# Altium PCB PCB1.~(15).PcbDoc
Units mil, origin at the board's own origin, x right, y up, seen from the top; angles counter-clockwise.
Board outline 3715 x 2925 mil, 2 copper layers (Top Layer, Bottom Layer); 4 components, 37 nets, 176 pads, 0 vias.
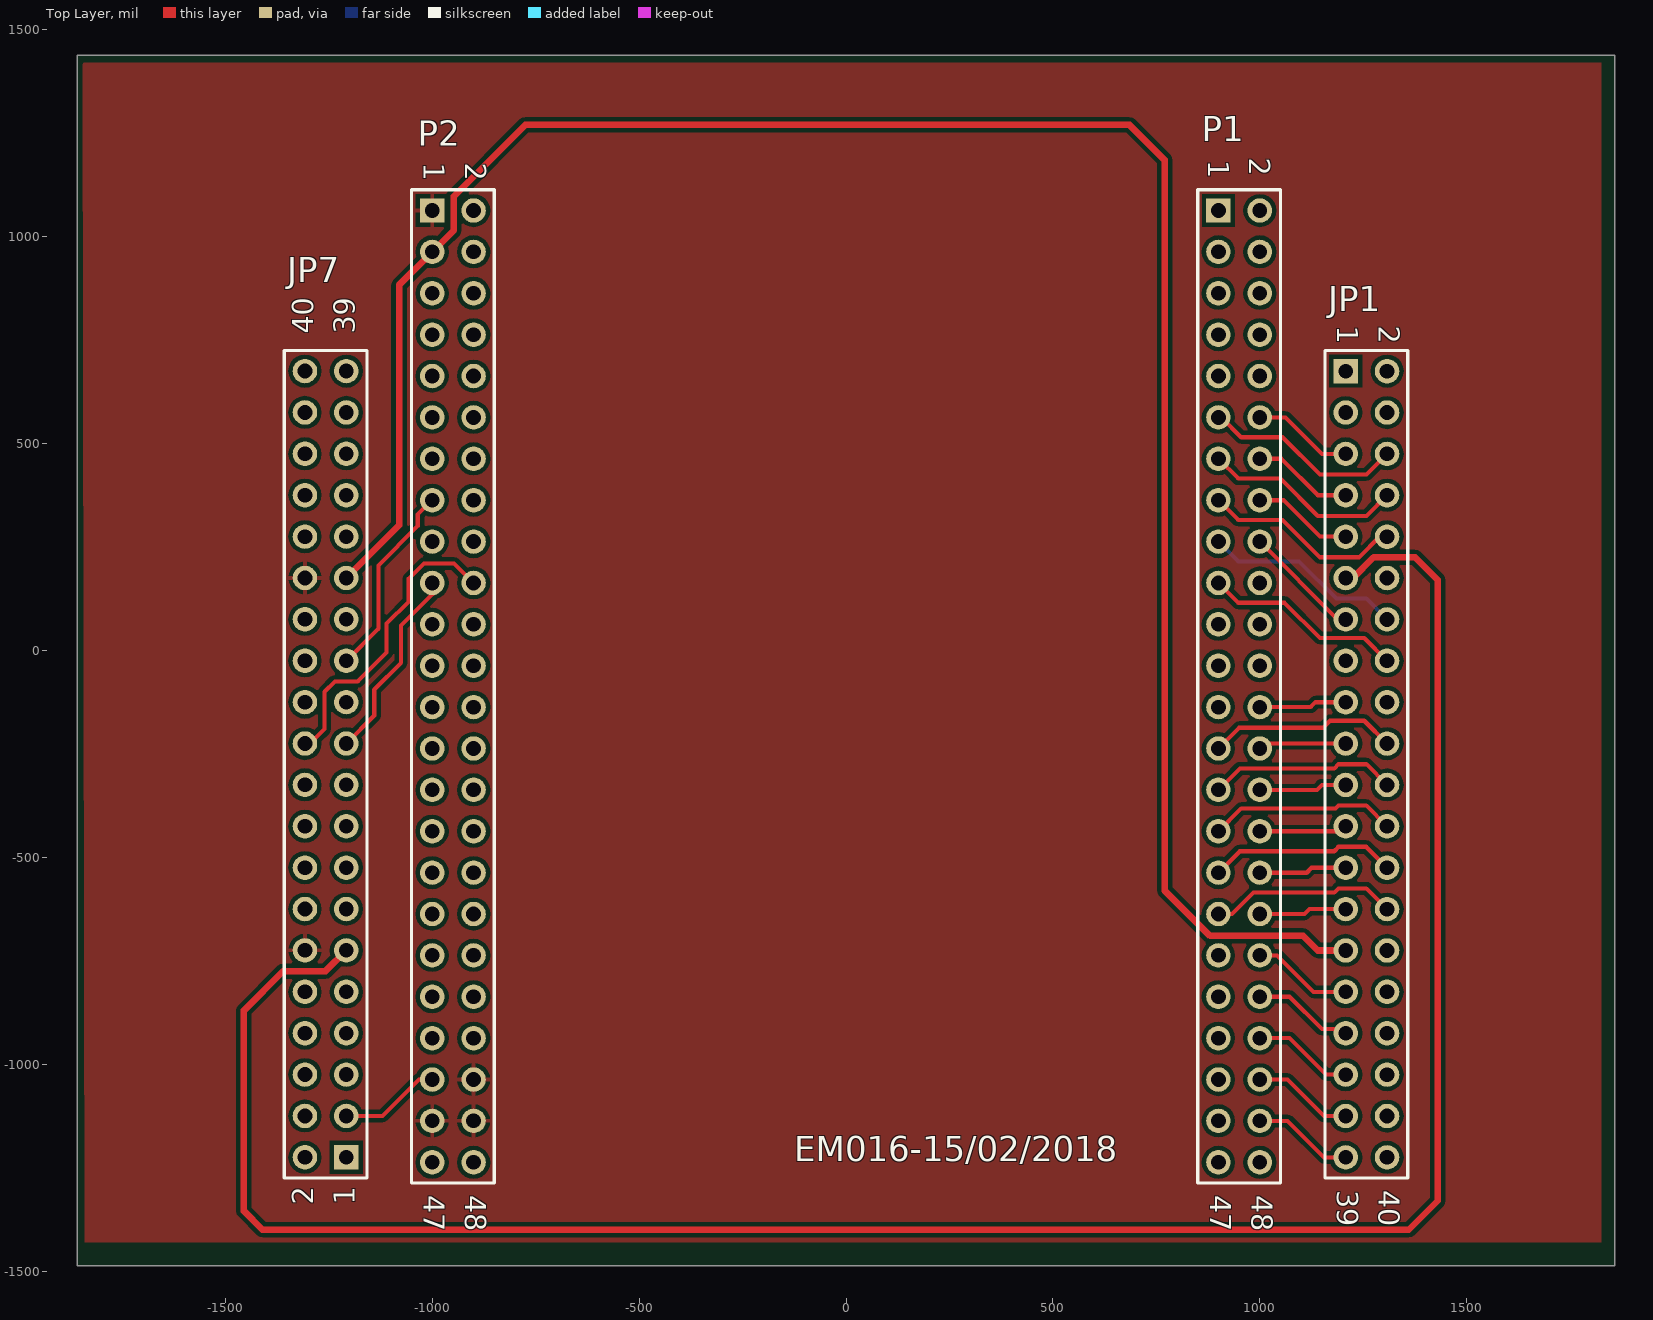
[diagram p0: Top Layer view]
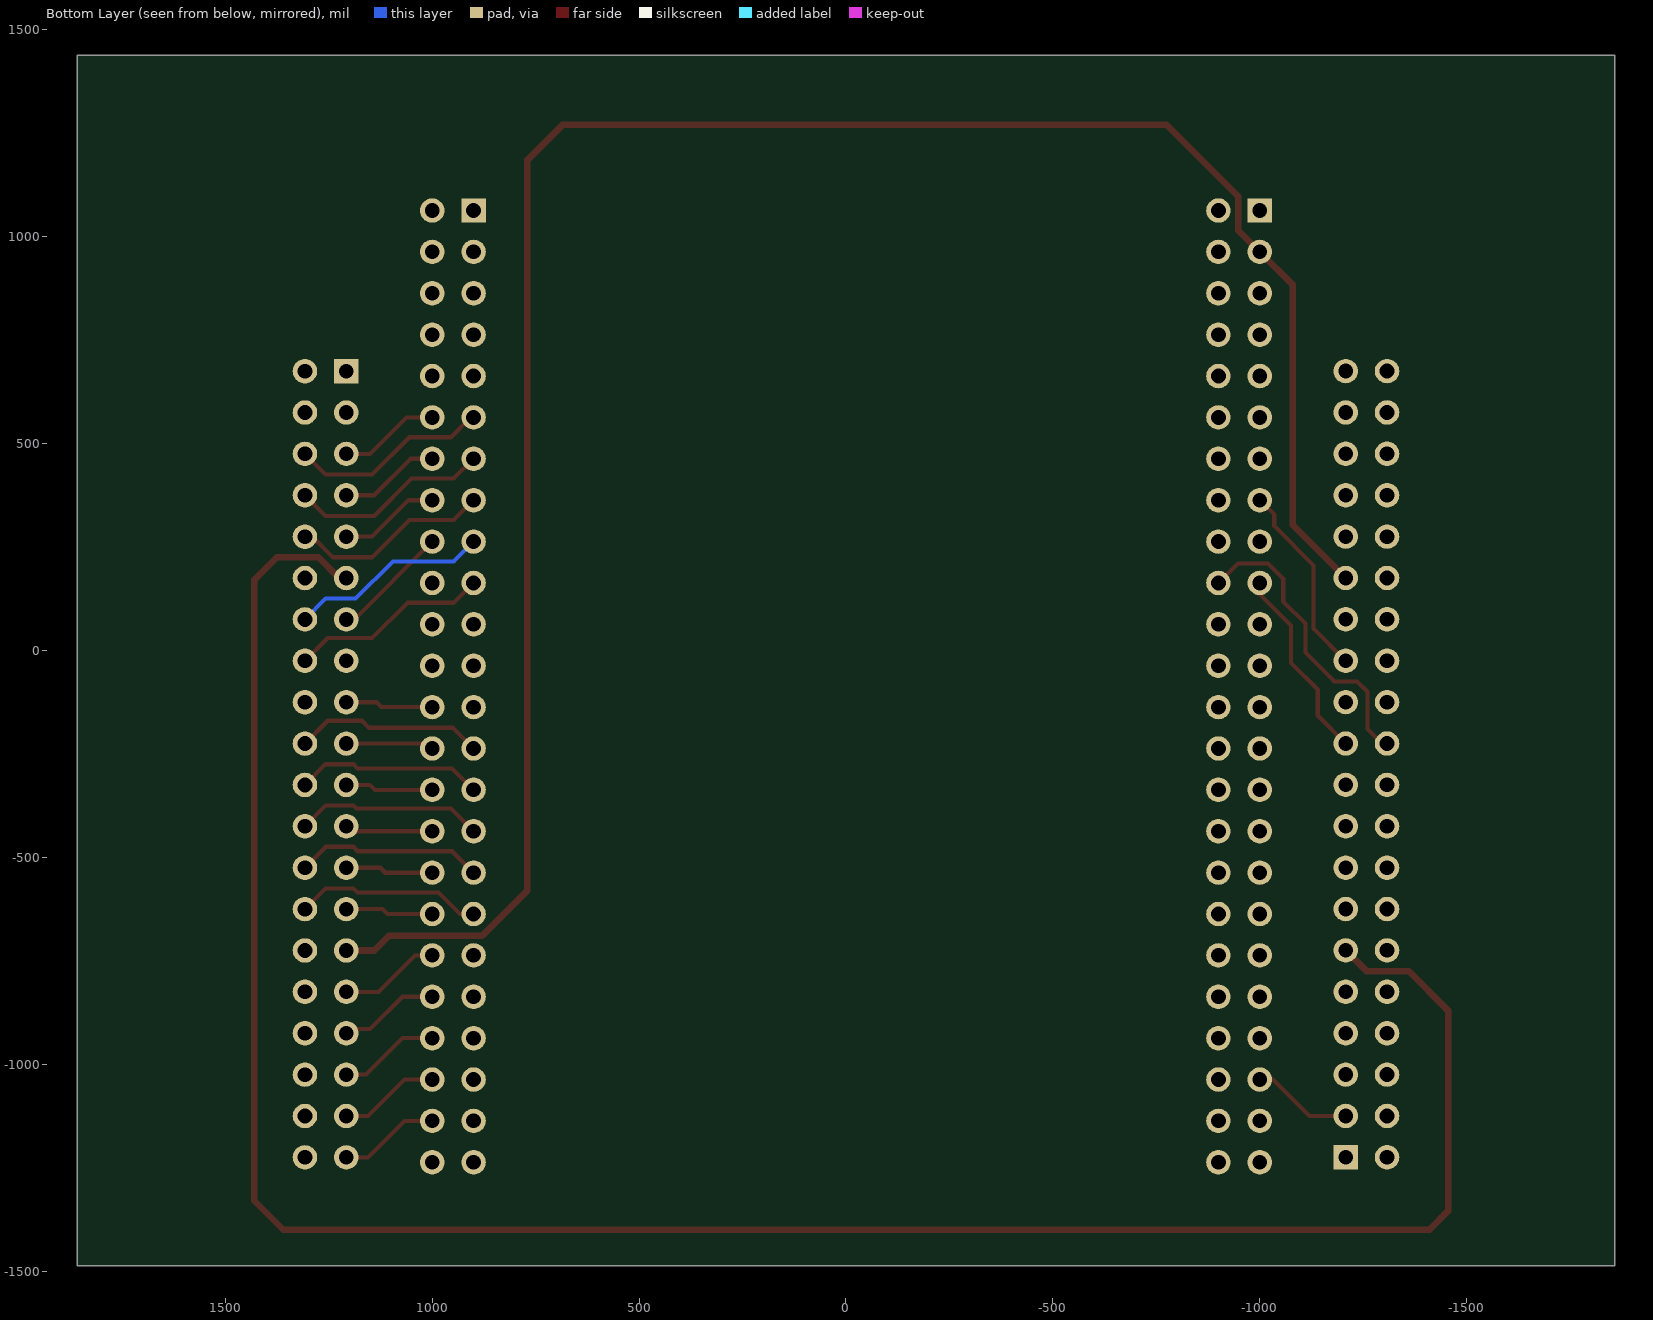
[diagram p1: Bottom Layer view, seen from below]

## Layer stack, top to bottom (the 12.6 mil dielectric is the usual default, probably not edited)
Top Solder: solder mask 0.4, Solder Resist, Dk 3.5
Top Layer: signal copper 1.4
Dielectric 1: dielectric 12.6, FR-4, Dk 4.8
Bottom Layer: signal copper 1.4
Bottom Solder: solder mask 0.4, Solder Resist, Dk 3.5

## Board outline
-1857.5,-1487.01 1857.5,-1487.01 1857.5,1437.99 -1857.5,1437.99

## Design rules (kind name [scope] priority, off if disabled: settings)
Clearance [All] p1: gap=10
PolygonConnect [All] p1: connectstyle=Relief reliefconductorwidth=10 reliefentries=4 polygonreliefangle="90 Angle" airgapwidth=10
RoomDefinition Sheet1 [InComponentClass('Sheet1')] p1 off: confinementstyle=ConfineIn formatcopy=TRUE lockcomponents=FALSE outline 4157.5,-2357.01 5522.5,-2357.01 5522.5,337.99 4157.5,337.99
RoutingVias [All] p1: holewidth=28 width=50 viastyle="Through Hole" minholewidth=28 minwidth=50 maxholewidth=28 maxwidth=50
SolderMaskExpansion [All] p1: expansion=4
Width [All] p1: maxlimit=25 minlimit=10 preferedwidth=10
30 further rules are at their usual default settings.

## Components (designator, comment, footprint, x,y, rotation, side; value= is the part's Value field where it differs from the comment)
JP1 "Header 20X2" HDR2X20 1207.48,674.84 r270 top
JP7 "Header 20X2" HDR2X20 -1207.48,-1225 r90 top
P1 "Header 24X2" HDR2X24 900,1062.99 r270 top
P2 "Header 24X2" HDR2X24 -1000,1062.99 r270 top

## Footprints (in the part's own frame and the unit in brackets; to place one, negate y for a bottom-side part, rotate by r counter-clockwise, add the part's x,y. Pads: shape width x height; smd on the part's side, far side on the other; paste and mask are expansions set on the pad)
HDR2X20 [mm] "Connector; Header; 20x2 Position"
  rect 1.5x1.5 hole 0.9: 1(0,0)
  round 1.5 hole 0.9: 2(0,2.54) 3(2.54,0) 4(2.54,2.54) 5(5.08,0) 6(5.08,2.54) 7(7.62,0) 8(7.62,2.54) 9(10.16,0) 10(10.16,2.54) 11(12.7,0) 12(12.7,2.54) 13(15.24,0) 14(15.24,2.54) 15(17.78,0) 16(17.78,2.54) 17(20.32,0) 18(20.32,2.54) 19(22.86,0) 20(22.86,2.54) 21(25.4,0) 22(25.4,2.54) 23(27.94,0) 24(27.94,2.54) 25(30.48,0) 26(30.48,2.54) 27(33.02,0) 28(33.02,2.54) 29(35.56,0) 30(35.56,2.54) 31(38.1,0) 32(38.1,2.54) 33(40.64,0) 34(40.64,2.54) 35(43.18,0) 36(43.18,2.54) 37(45.72,0) 38(45.72,2.54) 39(48.26,0) 40(48.26,2.54)
  silkscreen extent -1.27,-1.27 49.53,3.81
HDR2X24 [mm] "Connector; Header; 24x2 Position"
  rect 1.5x1.5 hole 0.9: 1(0,0)
  round 1.5 hole 0.9: 2(0,2.54) 3(2.54,0) 4(2.54,2.54) 5(5.08,0) 6(5.08,2.54) 7(7.62,0) 8(7.62,2.54) 9(10.16,0) 10(10.16,2.54) 11(12.7,0) 12(12.7,2.54) 13(15.24,0) 14(15.24,2.54) 15(17.78,0) 16(17.78,2.54) 17(20.32,0) 18(20.32,2.54) 19(22.86,0) 20(22.86,2.54) 21(25.4,0) 22(25.4,2.54) 23(27.94,0) 24(27.94,2.54) 25(30.48,0) 26(30.48,2.54) 27(33.02,0) 28(33.02,2.54) 29(35.56,0) 30(35.56,2.54) 31(38.1,0) 32(38.1,2.54) 33(40.64,0) 34(40.64,2.54) 35(43.18,0) 36(43.18,2.54) 37(45.72,0) 38(45.72,2.54) 39(48.26,0) 40(48.26,2.54) 41(50.8,0) 42(50.8,2.54) 43(53.34,0) 44(53.34,2.54) 45(55.88,0) 46(55.88,2.54) 47(58.42,0) 48(58.42,2.54)
  silkscreen extent -1.27,-1.27 59.69,3.81

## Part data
JP1 JP7: "Header, 20-Pin, Dual row"
P1 P2: "Header, 24-Pin, Dual row"

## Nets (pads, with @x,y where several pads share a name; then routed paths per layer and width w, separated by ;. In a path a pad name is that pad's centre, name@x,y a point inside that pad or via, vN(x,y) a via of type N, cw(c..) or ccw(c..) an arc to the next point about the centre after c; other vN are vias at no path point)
3.3V: JP1.29 JP7.29 P2.3 | length 5117.5
  Top Layer w16: JP7.29 -1080,302.48 -1080,882.99 P2.3 -947.53,1015.46 -947.53,1097.47 -775,1270 685,1270 770,1185 770,-580.21 879.79,-690 880.31,-689.48 1104.48,-689.48 1140.16,-725.16 JP1.29
DATA0: P1.45
DATA1: JP1.39 P1.46 | length 244
  Top Layer w10: P1.46 1067.01,-1137.01 1155.16,-1225.16 JP1.39
DATA2: P1.43
DATA3: JP1.37 P1.44 | length 244
  Top Layer w10: P1.44 1067.01,-1037.01 1155,-1125 1207.32,-1125 JP1.37
DATA4: P1.41
DATA5: JP1.35 P1.42 | length 244
  Top Layer w10: P1.42 1072.01,-937.01 1160.16,-1025.16 JP1.35
DATA6: P1.39
DATA7: JP1.33 P1.40 | length 244
  Top Layer w10: P1.40 1072.01,-837.01 1150,-915 1197.32,-915 JP1.33
DATA8: P1.37
DATA9: JP1.31 P1.38 | length 244
  Top Layer w10: P1.38 1041.69,-737.01 1129.84,-825.16 JP1.31
DATA10: JP1.27 P1.36 | length 212.4
  Top Layer w10: P1.36 1107.99,-637.01 1119.84,-625.16 JP1.27
DATA11: JP1.25 P1.34 | length 212.4
  Top Layer w11: P1.34 1112.99,-537.01 1124.84,-525.16 JP1.25
DATA12: JP1.28 P1.35 | length 453.9
  Top Layer w10: P1.35 932.99,-637.01 985,-585 1180,-585 1190,-575 1257.32,-575 JP1.28
DATA13: JP1.26 P1.33 | length 453.9
  Top Layer w11: P1.33 952.01,-485 1180,-485 1190,-475 1257.32,-475 JP1.26
DATA14: JP1.24 P1.31 | length 453.9
  Top Layer w10: P1.31 955,-382.01 1182.99,-382.01 1190,-375 1257.32,-375 JP1.24
DATA15: JP1.23 P1.32 | length 212.4
  Top Layer w10: P1.32 1195.63,-437.01 JP1.23
DATA16: JP1.10 P1.15 | length 485.3
  Top Layer w10: P1.15 947.99,315 1055,315 1145,225 1240,225 1289.84,274.84 JP1.10
DATA17: JP1.9 P1.16 | length 244
  Top Layer w10: P1.16 1057.01,362.99 1145.16,274.84 JP1.9
DATA18: JP1.6 P1.11 | length 485.3
  Top Layer w10: P1.11 907.01,562.99 955,515 1055,515 1145,425 1257.64,425 JP1.6
DATA19: JP1.5 P1.12 | length 244
  Top Layer w10: P1.12 1062.01,562.99 1150.16,474.84 JP1.5
DATA20: JP1.14 P1.17 | length 485.4
  Bottom Layer w10: P1.17 947.99,215 1095,215 1185,125 1257.32,125 JP1.14
DATA21: JP1.7 P1.14 | length 244
  Top Layer w10: P1.14 1052.01,462.99 1140.16,374.84 JP1.7
DATA22: JP1.8 P1.13 | length 485.3
  Top Layer w10: P1.13 947.99,415 1050,415 1140,325 1257.64,325 JP1.8
DATA23: JP1.16 P1.19 | length 485.4
  Top Layer w10: P1.19 947.99,115 1060,115 1145,30 1252.32,30 JP1.16
DATAEN: JP1.21 P1.30 | length 212.4
  Top Layer w10: P1.30 1137.99,-337.01 1149.84,-325.16 JP1.21
EXT_SCL: JP7.21 P2.19 | length 473.9
  Top Layer w10: JP7.21 -1140,-157.52 -1140,-95 -1075,-30 -1075,60 -1000,135 P2.19
EXT_SDA: JP7.22 P2.20 | length 733.1
  Top Layer w10: JP7.22 -1295,-225 -1260,-190 -1260,-100 -1235,-75 -1180,-75 -1110,-5 -1110,65 -1056.54,118.46 -1056.54,173.46 -1020,210 -947.01,210 P2.20
GND: JP7.12 JP7.30 P2.1 P2.44 P2.45 P2.46
GPIO5: JP1.13 P1.18 | length 285.4
  Top Layer w10: P1.18 1188.15,74.84 JP1.13
GPIO_INIT_DONE: JP1.17 P1.26 | length 212.4
  Top Layer w10: P1.26 1122.99,-137.01 1134.84,-125.16 JP1.17
HOST_PRESENT: JP7.3 P2.43 | length 243.9
  Top Layer w10: JP7.3 -1120,-1125 -1032.01,-1037.01 P2.43
HSYNC: JP1.22 P1.29 | length 453.9
  Top Layer w10: P1.29 952.01,-285 1180,-285 1190,-275 1257.32,-275 JP1.22
PCLK: JP1.19 P1.28 | length 212.4
  Top Layer w10: P1.28 1011.85,-225.16 JP1.19
PROJ_ON_EXT: JP7.25 P2.15 | length 473.9
  Top Layer w10: JP7.25 -1130,52.48 -1130,205.49 -1035,300.49 -1035,327.99 P2.15
VCC5: JP1.11 JP7.11 | length 5491.3
  Top Layer w16: JP7.11 -1257.48,-775 -1360,-775 -1455,-870 -1455,-1355 -1410,-1400 1360,-1400 1430,-1330 1430,170 1375,225 1275,225 1224.84,174.84 JP1.11
VSYNC: JP1.20 P1.27 | length 458.1
  Top Layer w10: P1.27 950,-187.01 1152.99,-187.01 1170,-170 1252.32,-170 JP1.20
pads on no net: JP1.1 JP1.2 JP1.3 JP1.4 JP1.12 JP1.15 JP1.18 JP1.30 JP1.32 JP1.34 JP1.36 JP1.38 JP1.40 JP7.1 JP7.2 JP7.4 JP7.5 JP7.6 JP7.7 JP7.8 JP7.9 JP7.10 JP7.13 JP7.14 JP7.15 JP7.16 JP7.17 JP7.18 JP7.19 JP7.20 JP7.23 JP7.24 JP7.26 JP7.27 JP7.28 JP7.31 JP7.32 JP7.33 JP7.34 JP7.35 JP7.36 JP7.37 JP7.38 JP7.39 JP7.40 P1.1 P1.2 P1.3 P1.4 P1.5 P1.6 P1.7 P1.8 P1.9 P1.10 P1.20 P1.21 P1.22 P1.23 P1.24 P1.25 P1.47 P1.48 P2.2 P2.4 P2.5 P2.6 P2.7 P2.8 P2.9 P2.10 P2.11 P2.12 P2.13 P2.14 P2.16 P2.17 P2.18 P2.21 P2.22 P2.23 P2.24 P2.25 P2.26 P2.27 P2.28 P2.29 P2.30 P2.31 P2.32 P2.33 P2.34 P2.35 P2.36 P2.37 P2.38 P2.39 P2.40 P2.41 P2.42 P2.47 P2.48

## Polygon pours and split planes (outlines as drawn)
GND on Top Layer "Top Layer-No Net" (solid, pour order 0): -1845,1420 1825,1420 1825,-1460 1825,-1430 -1840,-1430

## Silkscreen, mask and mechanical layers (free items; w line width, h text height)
Top Overlay:
  text "EM016-15/02/2018" at -125,-1235 h60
